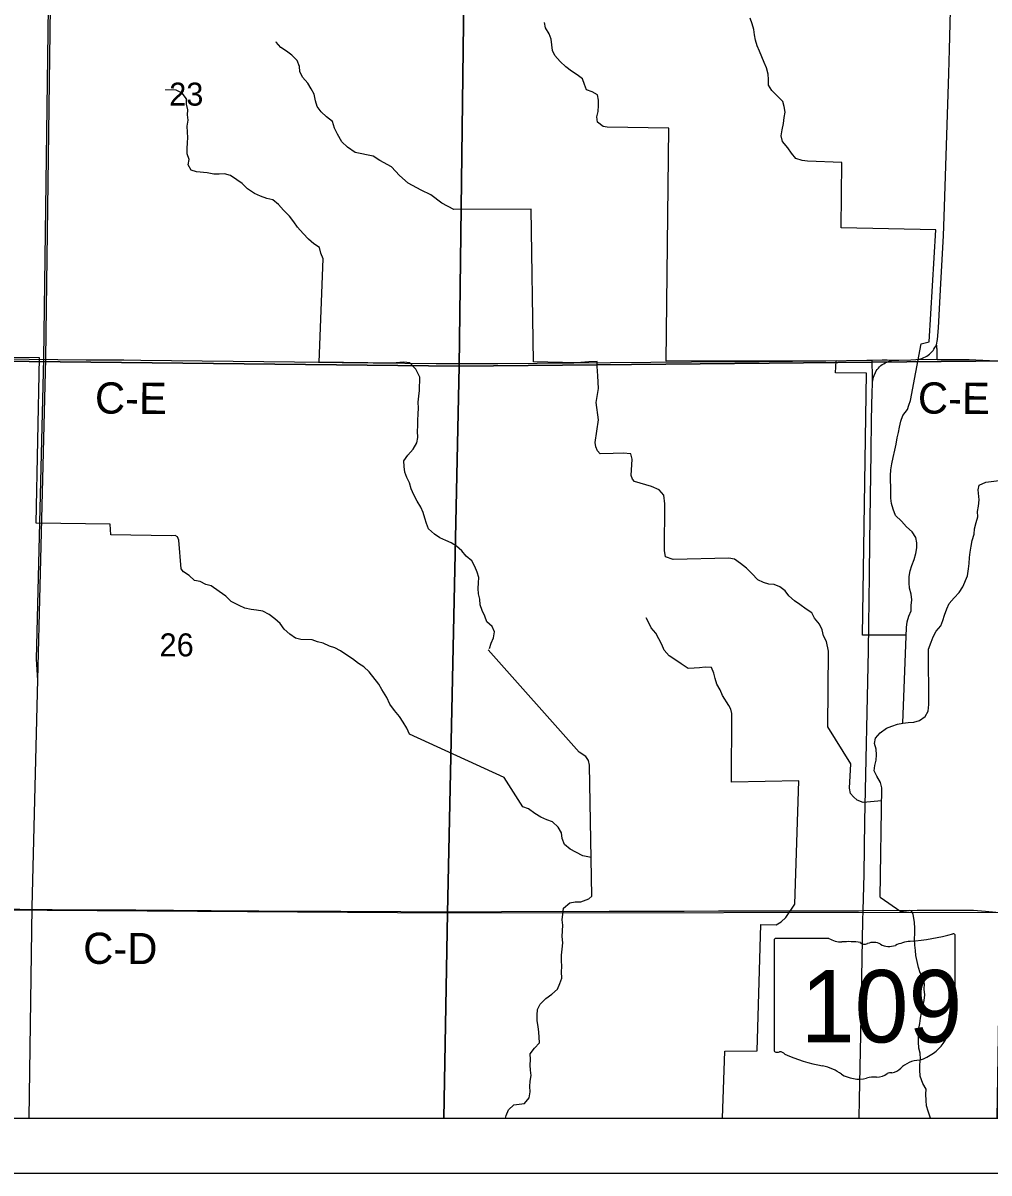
# Model space of a CAD drawing. Extents: x 0 to 42, y 0 to 22.
# Drawn here: x 4.409 to 6.167, y 14 to 16.093 of the extents above; entities that cross this region are included whole.
import ezdxf

# ---------------------------------------------------------------- set-up
doc = ezdxf.new("R2010")
doc.units = 0
for name, color, linetype in [('Default', 7, 'Continuous'), ('GM_X_County_Road', 7, 'Continuous'), ('GM_X_County_Road_Text', 7, 'Continuous'), ('GM_X_Interchange_Ramps', 7, 'Continuous'), ('GM_X_Minor_River', 7, 'Continuous'), ('GM_X_Rail_Line', 7, 'Continuous'), ('GM_X_Section', 7, 'Continuous'), ('GM_X_Section_Text', 7, 'Continuous'), ('GM_X_State_Location', 7, 'Continuous'), ('GM_X_State_Route', 7, 'Continuous'), ('GM_X_State_Shield', 7, 'Continuous'), ('GM_X_Township_Road', 7, 'Continuous'), ('SH_Data', 7, 'Continuous')]:
    doc.layers.add(name, color=color, linetype=linetype)

msp = doc.modelspace()

# ---------------------------------------------------------------- linework, layer by layer
at = {"layer": 'Default'}
for points in [[(4.1714, 14.1), (5.1749, 14.1), (5.1819, 14.4731), (4.179, 14.4795)], [(5.1749, 14.1), (6.1826, 14.1), (6.1876, 14.466), (6.1871, 14.4739), (5.1819, 14.4731)]]:
    msp.add_lwpolyline(points, close=True, dxfattribs=at)
at = {"layer": 'GM_X_County_Road'}
for points in [[(6.0728, 15.481), (6.0729, 15.4845), (6.0727, 15.4993), (6.0726, 15.5015), (6.0725, 15.5035), (6.0725, 15.5045), (6.0721, 15.5064), (6.0715, 15.5073)], [(4.1978, 15.484), (4.272, 15.4831), (4.3155, 15.4829), (4.3683, 15.4821), (4.5237, 15.4804), (4.5922, 15.48), (4.6232, 15.4796), (4.9031, 15.4763), (4.9901, 15.4754), (5.0461, 15.4746), (5.1612, 15.4735), (5.2731, 15.4735), (5.3446, 15.474), (5.4783, 15.4751), (5.6991, 15.4769), (5.7488, 15.4774), (5.8701, 15.4786), (5.9447, 15.4796), (5.9547, 15.4798)], [(5.9547, 15.4798), (5.9726, 15.4802), (5.982, 15.4799), (5.9918, 15.4794)], [(5.9551, 15.439), (5.9551, 15.4424), (5.9554, 15.4475), (5.9554, 15.4518), (5.9548, 15.4758), (5.9547, 15.4798)], [(5.9918, 15.4794), (5.9968, 15.4794), (6.0031, 15.4798), (6.0249, 15.48)], [(6.0249, 15.48), (6.0341, 15.4806), (6.0377, 15.4811)], [(6.0377, 15.4811), (6.0457, 15.4811), (6.0728, 15.481)], [(6.0728, 15.481), (6.1062, 15.4808), (6.131, 15.4805), (6.1684, 15.4792), (6.2065, 15.4773)], [(4.1791, 14.4815), (4.2477, 14.4811), (4.2788, 14.4811), (4.3409, 14.4806), (4.4031, 14.4801), (4.4621, 14.4799), (4.5461, 14.4791), (4.6145, 14.479), (4.6829, 14.4784), (4.7513, 14.4781), (4.8383, 14.4775), (4.9876, 14.4765), (5.0964, 14.476), (5.2021, 14.4755), (5.2798, 14.4758), (5.4757, 14.4765), (5.6125, 14.4769), (5.6747, 14.4771), (5.8208, 14.477), (5.9265, 14.4775), (5.9296, 14.4775), (5.9383, 14.4777)], [(5.9383, 14.4777), (6.0367, 14.4782), (6.1238, 14.4786), (6.1393, 14.4782), (6.1611, 14.4767), (6.1797, 14.4748), (6.1885, 14.4738)]]:
    msp.add_lwpolyline(points, dxfattribs=at)
at = {"layer": 'GM_X_Interchange_Ramps'}
msp.add_lwpolyline([(2.1, 18.5138), (2.1, 14.1), (6.182, 14.1), (6.1883, 14.4744), (6.2063, 15.4779), (6.2205, 16.2146)], dxfattribs=at)
at = {"layer": 'GM_X_Minor_River'}
for points in [[(5.8368, 15.8418), (5.827, 15.8432), (5.8157, 15.8465), (5.8079, 15.8561), (5.8009, 15.8658), (5.7917, 15.8774), (5.7889, 15.8881), (5.7911, 15.8986), (5.7933, 15.9104), (5.7947, 15.9213), (5.7964, 15.9312), (5.7947, 15.9411), (5.7919, 15.9506), (5.7823, 15.9599), (5.7719, 15.9704), (5.7661, 15.9804), (5.7659, 15.9907), (5.7654, 16.0002), (5.7622, 16.012), (5.7579, 16.0216), (5.754, 16.0316), (5.7497, 16.0419), (5.7453, 16.0515), (5.7422, 16.0622), (5.7405, 16.0717), (5.7392, 16.0812), (5.7364, 16.0919), (5.7325, 16.1023)], [(5.4721, 15.9039), (5.4649, 15.9048), (5.4545, 15.913), (5.4532, 15.9225), (5.4557, 15.9323), (5.4567, 15.9429), (5.4562, 15.9528), (5.4545, 15.9627), (5.4448, 15.9683), (5.4346, 15.9719), (5.4311, 15.9815), (5.4275, 15.9918), (5.4178, 15.9992), (5.4074, 16.0059), (5.3969, 16.0137), (5.3865, 16.0235), (5.3769, 16.0339), (5.3729, 16.0435), (5.3704, 16.064), (5.3664, 16.0736), (5.3602, 16.0844), (5.3582, 16.0943)], [(4.9993, 15.867), (4.9893, 15.8771), (4.9813, 15.8909), (4.9762, 15.9021), (4.9723, 15.9139), (4.9615, 15.9225), (4.9515, 15.9318), (4.9441, 15.9415), (4.9413, 15.9514), (4.9386, 15.9636), (4.9335, 15.9736), (4.9273, 15.984), (4.9176, 15.9945), (4.913, 16.0048), (4.912, 16.0143), (4.9077, 16.025), (4.8985, 16.0347), (4.8884, 16.0422), (4.8783, 16.0485), (4.8698, 16.0582), (4.8694, 16.0585)], [(4.9551, 15.6641), (4.9511, 15.6741), (4.9484, 15.6848), (4.9383, 15.6915), (4.9286, 15.6997), (4.919, 15.7101), (4.9086, 15.7217), (4.9016, 15.7314), (4.8939, 15.7418), (4.8832, 15.7527), (4.8739, 15.7628), (4.8639, 15.7713), (4.8526, 15.7739), (4.8409, 15.7783), (4.83, 15.7827), (4.8177, 15.7913), (4.8077, 15.8011), (4.7979, 15.8077), (4.7864, 15.816), (4.7758, 15.8185), (4.7659, 15.8179), (4.7561, 15.8181), (4.7444, 15.8203), (4.7247, 15.8223), (4.7149, 15.8255), (4.7098, 15.8351), (4.7116, 15.845), (4.708, 15.8553), (4.7075, 15.8648), (4.7081, 15.875), (4.7087, 15.8849), (4.7082, 15.8944), (4.7077, 15.9058), (4.7094, 15.9164), (4.7085, 15.9259), (4.7087, 15.9354), (4.7063, 15.9457), (4.7062, 15.9555), (4.6984, 15.9656), (4.6876, 15.9711), (4.6686, 15.9716), (4.6682, 15.9708)], [(6.0167, 14.9788), (5.9372, 14.979), (5.9443, 15.456), (5.8877, 15.4565), (5.889, 15.4785), (5.5798, 15.4775), (5.5848, 15.9017), (5.4721, 15.9039)], [(5.1932, 15.7541), (5.1714, 15.7656), (5.1513, 15.7805), (5.1337, 15.7888), (5.1097, 15.8015), (5.0941, 15.8159), (5.0796, 15.8314), (5.0587, 15.8433), (5.0463, 15.8511), (5.0137, 15.8578), (4.9993, 15.867)], [(6.0243, 15.4064), (6.0438, 15.5096), (6.0586, 15.5127), (6.0706, 15.717), (5.8985, 15.7205), (5.8997, 15.8393), (5.8368, 15.8418)], [(5.6935, 15.1189), (5.5926, 15.1169), (5.5786, 15.1218), (5.5766, 15.1332), (5.5771, 15.2183), (5.5756, 15.2339), (5.5671, 15.2435), (5.5532, 15.2495), (5.5223, 15.2586), (5.5182, 15.2632), (5.5161, 15.2694), (5.5179, 15.2993), (5.5155, 15.3092), (5.5011, 15.3103), (5.4829, 15.3096), (5.4597, 15.3093), (5.4549, 15.3144), (5.4517, 15.3217), (5.4507, 15.33), (5.4562, 15.3709), (5.452, 15.4025), (5.4564, 15.4278), (5.4555, 15.451), (5.454, 15.4681), (5.4542, 15.4769), (5.439, 15.4768), (5.4169, 15.475), (5.3381, 15.4768), (5.3336, 15.7544), (5.1932, 15.7541)], [(5.1314, 15.4488), (5.1241, 15.4634), (5.1131, 15.4746), (5.1021, 15.476), (5.0808, 15.4742), (4.948, 15.476), (4.9551, 15.6641)], [(4.6965, 15.0998), (4.6927, 15.1519), (4.6903, 15.1577), (4.686, 15.1604), (4.6788, 15.1601), (4.5688, 15.1618), (4.5678, 15.1808), (4.4327, 15.1827), (4.4387, 15.484), (3.6765, 15.4885)], [(5.2579, 14.9547), (5.2612, 14.9645), (5.2652, 14.9743), (5.2673, 14.9853), (5.263, 14.9949), (5.253, 15.0034), (5.2498, 15.0138), (5.2447, 15.0237), (5.2412, 15.0345), (5.2407, 15.0443), (5.2379, 15.0543), (5.2373, 15.0641), (5.2379, 15.074), (5.2389, 15.0842), (5.2357, 15.0938), (5.2314, 15.1041), (5.226, 15.1141), (5.2156, 15.1227), (5.2078, 15.1324), (5.1982, 15.1413), (5.1884, 15.1472), (5.1783, 15.1513), (5.1678, 15.156), (5.1577, 15.1627), (5.1473, 15.1728), (5.1434, 15.1824), (5.1405, 15.192), (5.137, 15.2023), (5.1331, 15.2122), (5.1261, 15.223), (5.1203, 15.2342), (5.1156, 15.2453), (5.1125, 15.2564), (5.1074, 15.266), (5.1042, 15.2759), (5.1025, 15.2862), (5.102, 15.2965), (5.1095, 15.3065), (5.1188, 15.3177), (5.1256, 15.329), (5.1273, 15.3388), (5.1272, 15.3502), (5.1278, 15.36), (5.1276, 15.3695), (5.1279, 15.3817), (5.1289, 15.3923), (5.1284, 15.4033), (5.1294, 15.4139), (5.1308, 15.4241), (5.1314, 15.4488)], [(6.0172, 14.9932), (6.0186, 15.003), (6.0215, 15.0136), (6.0255, 15.0234), (6.0254, 15.0329), (6.0267, 15.0431), (6.0259, 15.0537), (6.0223, 15.0644), (6.0222, 15.0743), (6.0221, 15.0857), (6.0238, 15.0959), (6.0267, 15.1061), (6.0308, 15.1166), (6.0344, 15.1276), (6.0358, 15.1378), (6.036, 15.1473), (6.0344, 15.1568), (6.0274, 15.1672), (6.0174, 15.1765), (6.0081, 15.1866), (5.9974, 15.1971), (5.9927, 15.2082), (5.9899, 15.2185), (5.9886, 15.2284), (5.9885, 15.2394), (5.9884, 15.2497), (5.9878, 15.26), (5.9877, 15.2694), (5.9887, 15.2797), (5.9905, 15.291), (5.9926, 15.3024), (5.9956, 15.316), (5.9981, 15.3265), (6.0003, 15.3379), (6.0028, 15.3477), (6.0042, 15.3575), (6.0067, 15.3685), (6.0107, 15.3786), (6.0189, 15.3899), (6.0212, 15.3976), (6.0243, 15.4064)], [(6.1613, 15.2576), (6.2001, 15.2625)], [(6.0573, 14.9536), (6.0621, 14.9664), (6.0654, 14.9762), (6.0709, 14.9863), (6.0795, 14.996), (6.0832, 15.0058), (6.0864, 15.0156), (6.0905, 15.0269), (6.0949, 15.0366), (6.1042, 15.0467), (6.1128, 15.0564), (6.1199, 15.0668), (6.1279, 15.0871), (6.1298, 15.0996), (6.1311, 15.1095), (6.1318, 15.1205), (6.1328, 15.1303), (6.1349, 15.1409), (6.1367, 15.1511), (6.1403, 15.1628), (6.141, 15.1726), (6.1439, 15.184), (6.1468, 15.1941), (6.1466, 15.204), (6.148, 15.2139), (6.1494, 15.2252), (6.1473, 15.2436), (6.1493, 15.2522), (6.1613, 15.2576)], [(5.8751, 14.9497), (5.8713, 14.9672), (5.8662, 14.978), (5.8638, 14.9887), (5.8588, 14.999), (5.8496, 15.0102), (5.8448, 15.0198), (5.8344, 15.0265), (5.8232, 15.0347), (5.8131, 15.0418), (5.8031, 15.0504), (5.7961, 15.06), (5.7864, 15.0671), (5.7762, 15.0711), (5.7664, 15.0721), (5.7566, 15.0749), (5.7468, 15.0796), (5.7357, 15.091), (5.7261, 15.1007), (5.7152, 15.1096), (5.7038, 15.1172), (5.6935, 15.1189)], [(5.1123, 14.7989), (5.1077, 14.8097), (5.1011, 14.8208), (5.0945, 14.8312), (5.0849, 14.8421), (5.0768, 14.8536), (5.071, 14.8655), (5.0619, 14.8802), (5.0568, 14.8898), (5.0391, 14.9122), (5.0295, 14.9211), (5.0194, 14.9274), (5.0086, 14.936), (4.9985, 14.9423), (4.9869, 14.9506), (4.9764, 14.9557), (4.9666, 14.959), (4.955, 14.9645), (4.9452, 14.967), (4.9354, 14.9707), (4.9145, 14.9711), (4.9047, 14.9733), (4.8947, 14.9811), (4.8843, 14.99), (4.8769, 15.0001), (4.8672, 15.0086), (4.8568, 15.0165), (4.8456, 15.0224), (4.8338, 15.0246), (4.824, 15.0259), (4.8127, 15.0281), (4.8022, 15.0329), (4.7875, 15.0404), (4.7779, 15.0501), (4.766, 15.0584), (4.7514, 15.0689), (4.7416, 15.0714), (4.7311, 15.0766), (4.7213, 15.0787), (4.7116, 15.0877), (4.7012, 15.094), (4.6965, 15.0998)], [(5.6823, 14.869), (5.678, 14.8793), (5.6718, 14.8897), (5.6686, 14.9), (5.6666, 14.9099), (5.6619, 14.9203), (5.6509, 14.9209), (5.6403, 14.9196), (5.6304, 14.9191), (5.6198, 14.9186), (5.6067, 14.9268), (5.5955, 14.9347), (5.585, 14.9414), (5.5758, 14.9518), (5.5715, 14.9622), (5.566, 14.9722), (5.5606, 14.9825), (5.5521, 14.9926), (5.5466, 15.0037), (5.543, 15.0106)], [(6.0105, 14.8191), (6.0172, 14.9932)], [(5.4399, 14.7423), (5.4382, 14.7507), (5.4335, 14.7584), (5.4215, 14.7658), (5.2556, 14.9521)], [(5.9717, 14.6776), (5.9384, 14.6742), (5.9271, 14.6786), (5.9208, 14.6845), (5.9153, 14.691), (5.9136, 14.7006), (5.9158, 14.7449), (5.8737, 14.8123), (5.8751, 14.9497)], [(6.0579, 14.8526), (6.0573, 14.9536)], [(5.6821, 14.1), (5.6864, 14.222), (5.7453, 14.2226), (5.7518, 14.4525), (5.7799, 14.4519), (5.7887, 14.4574), (5.7976, 14.4651), (5.8141, 14.4891), (5.8213, 14.7136), (5.6984, 14.7114), (5.6994, 14.8364), (5.6973, 14.8443), (5.6937, 14.851), (5.6823, 14.869)], [(5.972, 14.7012), (5.97, 14.7111), (5.963, 14.7222), (5.9583, 14.7318), (5.9597, 14.7417), (5.9618, 14.7515), (5.9625, 14.7613), (5.9619, 14.7716), (5.9588, 14.7819), (5.9605, 14.7918), (5.9691, 14.8014), (5.9807, 14.8095), (5.9902, 14.8135), (6.0006, 14.8171), (6.0105, 14.8191), (6.02, 14.82), (6.0306, 14.8206), (6.0406, 14.8234), (6.051, 14.8311), (6.0565, 14.8409), (6.0579, 14.8526)], [(5.319, 14.6668), (5.285, 14.7199), (5.1123, 14.7989)], [(5.4442, 14.5042), (5.4399, 14.7423)], [(5.9693, 14.5023), (5.972, 14.7012)], [(5.4429, 14.5745), (5.4277, 14.5774), (5.4153, 14.5838), (5.4049, 14.5897), (5.3944, 14.5979), (5.3901, 14.6086), (5.3892, 14.6193), (5.383, 14.6297), (5.3726, 14.639), (5.3625, 14.6427), (5.3512, 14.6475), (5.3404, 14.6542), (5.3292, 14.6631), (5.319, 14.6668)], [(5.2873, 14.1), (5.2884, 14.1049), (5.2924, 14.1147), (5.3021, 14.1243), (5.312, 14.1252), (5.3215, 14.1265), (5.3305, 14.137), (5.3319, 14.148), (5.3317, 14.1574), (5.3319, 14.1673), (5.3337, 14.1775), (5.3324, 14.187), (5.3322, 14.1965), (5.3329, 14.2068), (5.332, 14.217), (5.3402, 14.2271), (5.3491, 14.2368), (5.3482, 14.247), (5.3481, 14.2565), (5.3468, 14.2668), (5.3448, 14.2771), (5.345, 14.2874), (5.3456, 14.2976), (5.3504, 14.3074), (5.3605, 14.3174), (5.3713, 14.3255), (5.3818, 14.3347), (5.3862, 14.3449), (5.3895, 14.3547), (5.3894, 14.3661), (5.3896, 14.3756), (5.3891, 14.387), (5.3893, 14.3968), (5.3903, 14.4074), (5.3917, 14.4192), (5.3905, 14.4306), (5.3907, 14.4408), (5.3914, 14.4511), (5.3901, 14.461), (5.3918, 14.4712), (5.3928, 14.4818), (5.4045, 14.4918), (5.414, 14.4935), (5.4246, 14.4936), (5.4389, 14.4992), (5.4442, 14.5042)], [(5.9693, 14.5023), (6.007, 14.476), (6.0222, 14.478)], [(6.061, 14.1), (6.0593, 14.1032), (6.0568, 14.1128), (6.0536, 14.1223), (6.0531, 14.1318), (6.0526, 14.1432), (6.0528, 14.1527), (6.0466, 14.1631), (6.042, 14.1761), (6.0411, 14.1875), (6.0417, 14.1974), (6.0427, 14.2072), (6.0422, 14.2179), (6.0394, 14.2274), (6.0389, 14.2388), (6.0388, 14.2498), (6.0391, 14.2605), (6.0412, 14.2722), (6.0426, 14.282), (6.0447, 14.2918), (6.0469, 14.3032), (6.049, 14.3138), (6.0508, 14.3243), (6.0495, 14.3346), (6.0501, 14.3445), (6.0473, 14.354), (6.0423, 14.3644), (6.0387, 14.3743), (6.0367, 14.385), (6.0339, 14.3957), (6.0337, 14.4052), (6.0321, 14.4147), (6.0319, 14.4257), (6.0322, 14.4364), (6.032, 14.4459), (6.0315, 14.4557), (6.0291, 14.4709), (6.0262, 14.4767), (6.0222, 14.478)]]:
    msp.add_lwpolyline(points, dxfattribs=at)
at = {"layer": 'GM_X_Rail_Line'}
for points in [[(4.4201, 14.1), (4.4258, 14.4841), (4.4505, 15.4825), (4.4609, 16.2603), (4.4628, 16.4862), (4.4739, 16.927), (4.4741, 16.9438), (4.4795, 17.4845), (4.5072, 18.7551), (4.5183, 19.5978), (4.5387, 20.5461), (4.5449, 20.9)], [(4.436, 14.8964), (4.4332, 14.9355), (4.4468, 15.4826), (4.4572, 16.2603), (4.4591, 16.4863), (4.4702, 16.9271), (4.4703, 16.9438), (4.4738, 17.1251), (4.4738, 17.1392), (4.4763, 17.1728)]]:
    msp.add_lwpolyline(points, dxfattribs=at)
at = {"layer": 'GM_X_Section'}
for points in [[(4.2153, 16.4855), (5.2156, 16.4769), (5.2026, 15.4687), (4.1963, 15.4797)], [(6.224, 16.494), (6.2249, 16.4863), (6.2056, 15.4786), (5.2026, 15.4687), (5.2156, 16.4769), (5.6923, 16.4799)], [(5.2026, 15.4687), (5.1819, 14.4731), (4.179, 14.4795), (4.1963, 15.4797)], [(6.2056, 15.4786), (6.1871, 14.4739), (5.1819, 14.4731), (5.2026, 15.4687)]]:
    msp.add_lwpolyline(points, close=True, dxfattribs=at)
at = {"layer": 'GM_X_State_Route'}
for points in [[(6.0377, 15.4811), (6.0402, 15.4815), (6.0431, 15.4823), (6.046, 15.4832), (6.0489, 15.4843), (6.0516, 15.4856), (6.0543, 15.4871), (6.0568, 15.4888), (6.0592, 15.4907), (6.0614, 15.4927), (6.0635, 15.4949), (6.0654, 15.4973), (6.0671, 15.4998), (6.0688, 15.5024), (6.0707, 15.5053), (6.0715, 15.5073), (6.0737, 15.5174), (6.0752, 15.5384), (6.0794, 15.6191), (6.0842, 15.7061), (6.0863, 15.7589), (6.0905, 15.8894), (6.0941, 16.0013), (6.0955, 16.0448), (6.0973, 16.1162)], [(5.931, 14.1), (5.9316, 14.1335), (5.9337, 14.2516), (5.9379, 14.4599), (5.9383, 14.4777), (5.9398, 14.5438), (5.9415, 14.6402), (5.9477, 14.951), (5.9484, 14.9976), (5.95, 15.0877), (5.9506, 15.1499), (5.953, 15.3116), (5.9536, 15.3707), (5.9545, 15.4214), (5.9551, 15.436), (5.9551, 15.439), (5.9558, 15.4423), (5.9572, 15.4485), (5.9581, 15.4515), (5.9606, 15.4573), (5.9622, 15.4601), (5.964, 15.4627), (5.966, 15.4652), (5.9682, 15.4675), (5.9705, 15.4696), (5.9731, 15.4715), (5.9757, 15.4732), (5.9785, 15.4747), (5.9814, 15.476), (5.9844, 15.4771), (5.9918, 15.4794)], [(5.9918, 15.4794), (5.9968, 15.4794), (6.0031, 15.4798), (6.0249, 15.48)], [(6.0249, 15.48), (6.0341, 15.4806), (6.0377, 15.4811)]]:
    msp.add_lwpolyline(points, dxfattribs=at)
at = {"layer": 'GM_X_State_Shield'}
for p, q in [((5.7761, 14.4236), (5.7761, 14.2235)), ((5.8759, 14.4271), (5.7794, 14.4271)), ((6.1057, 14.3273), (6.1057, 14.432)), ((6.1057, 14.3274), (6.1057, 14.3273))]:
    msp.add_line(p, q, dxfattribs=at)
for centre, major_axis, start_param, end_param in [((5.7799, 14.4241), (0.00382, 0), 1.712693, 3.28349), ((5.8989, 14.4503), (0.037, 0), 4.042523, 4.731795), ((5.9883, 14.6999), (0.3495, 0), 4.814394, 5.042369), ((6.1021, 14.4325), (0.00367, 0), 6.141152, 7.989035), ((5.9112, 14.3147), (0.133, 0), 1.404758, 1.657858), ((5.9413, 14.4251), (0.0107, 0), 3.836095, 5.185415), ((5.957, 14.402), (0.0222, 0), 0.950623, 2.079405), ((5.9857, 14.4337), (0.0267, 0), 4.081561, 5.145723), ((6.0329, 14.3659), (0.0703, 0), 1.699011, 2.107814), ((6.1049, 14.3197), (0.00568, 0), 1.883978, 3.671073), ((6.1018, 14.3269), (0.00393, 0), 5.05454, 6.418171), ((6.0687, 14.3064), (0.0341, 0), 5.934695, 6.695948), ((6.0079, 14.2702), (0.0874, 0), 5.101752, 6.440018), ((6.1189, 14.2835), (0.0248, 0), 2.387724, 3.262537), ((5.7799, 14.2231), (0.00385, 0), 3.00124, 4.508301), ((5.7805, 14.2435), (0.0294, 0), 4.665946, 4.897461), ((5.7865, 14.212), (0.0106, 0), 0.519207, 1.627899), ((5.9204, 14.3918), (0.2524, 0), 4.195997, 4.488961), ((5.8451, 14.1336), (0.079, 0), 0.823519, 1.323587), ((6.0448, 14.1673), (0.0479, 0), 1.647645, 2.488434), ((5.9305, 14.211), (0.0501, 0), 4.026481, 4.996735), ((5.9595, 14.1418), (0.0412, 0), 1.495662, 1.94098), ((5.9631, 14.196), (0.0267, 0), 4.691044, 5.507374), ((5.9873, 14.1766), (0.00752, 0), 1.147584, 2.315152), ((5.9841, 14.2041), (0.0282, 0), 4.937069, 5.64225)]:
    msp.add_ellipse(centre, major_axis=major_axis, ratio=0.8, start_param=start_param, end_param=end_param, dxfattribs=at)
at = {"layer": 'GM_X_Township_Road'}
for points in [[(4.1978, 15.484), (4.272, 15.4831), (4.3155, 15.4829), (4.3683, 15.4821), (4.5237, 15.4804), (4.5922, 15.48), (4.6232, 15.4796), (4.9031, 15.4763), (4.9901, 15.4754), (5.0461, 15.4746), (5.1612, 15.4735), (5.2731, 15.4735), (5.3446, 15.474), (5.4783, 15.4751), (5.6991, 15.4769), (5.7488, 15.4774), (5.8701, 15.4786), (5.9447, 15.4796), (5.9547, 15.4798)], [(5.9547, 15.4798), (5.9726, 15.4802), (5.982, 15.4799), (5.9918, 15.4794)], [(5.9918, 15.4794), (5.9968, 15.4794), (6.0031, 15.4798), (6.0249, 15.48)], [(6.0249, 15.48), (6.0341, 15.4806), (6.0377, 15.4811)], [(6.0377, 15.4811), (6.0457, 15.4811), (6.0728, 15.481)], [(6.0728, 15.481), (6.1062, 15.4808), (6.131, 15.4805), (6.1684, 15.4792), (6.2065, 15.4773)]]:
    msp.add_lwpolyline(points, dxfattribs=at)
at = {"layer": 'SH_Data'}
for p, q in [((2.1, 14.1), (8.9, 14.1)), ((2, 14), (9, 14))]:
    msp.add_line(p, q, dxfattribs=at)

# ---------------------------------------------------------------- texts
at = {"layer": 'GM_X_County_Road_Text'}
for s, rotation, p in [('C-E', 359.5714, (4.5397, 15.3825)), ('C-E', 359.577, (6.0378, 15.3825)), ('C-D', 359.5871, (4.5183, 14.3809))]:
    msp.add_text(s, height=0.05682, rotation=rotation, dxfattribs=at).set_placement(p)
at = {"layer": 'GM_X_Section_Text'}
for s, p in [('23', (4.6749, 15.9429)), ('26', (4.6574, 14.9404))]:
    msp.add_text(s, height=0.04186, rotation=0, dxfattribs=at).set_placement(p)
at = {"layer": 'GM_X_State_Location'}
for s in ['s', 'r']:
    msp.add_text(s, height=0.000189, dxfattribs=at).set_placement((5.9372, 14.3103))
msp.add_text('109', height=0.000189, rotation=0, dxfattribs=at).set_placement((5.8704, 14.2965))
at = {"layer": 'GM_X_State_Shield'}
msp.add_text('109', height=0.13184, dxfattribs=at).set_placement((5.8246, 14.2376))

doc.saveas('drawing.dxf')
